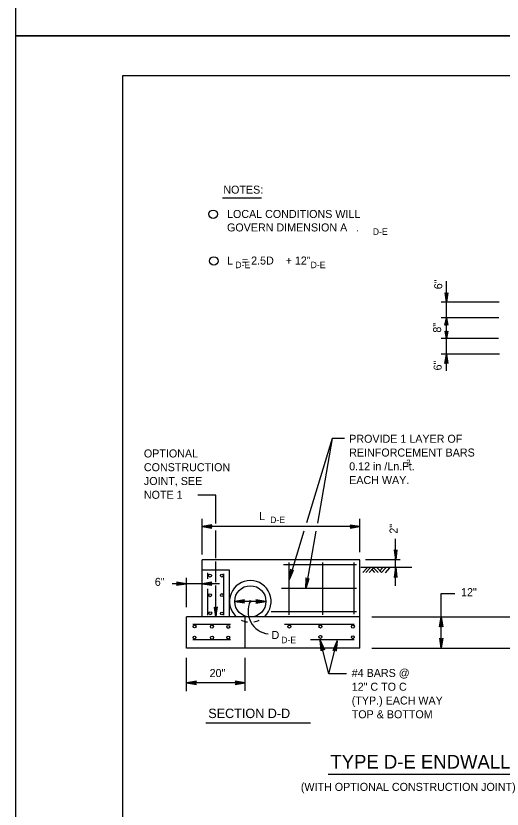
# Model space of a CAD drawing. Extents: x 638877 to 639960, y 297341 to 299123.
# Drawn here: x 638877.2 to 639059.3, y 298239.6 to 298536.8 of the extents above; entities that cross this region are included whole.
import ezdxf

# ---------------------------------------------------------------- set-up
doc = ezdxf.new("R2010")
doc.units = 0
for name, color, linetype in [('1', 7, 'Continuous'), ('2', 7, 'Continuous'), ('3', 7, 'Continuous'), ('PLT-BNDY', 7, 'Continuous')]:
    doc.layers.add(name, color=color, linetype=linetype)

msp = doc.modelspace()

# ---------------------------------------------------------------- linework, layer by layer
at = {"layer": '1'}
for p, q in [((639703.19, 298514.28), (638917.19, 298514.28)), ((638917.19, 298514.28), (638917.19, 297950.28)), ((639008.72, 298330.03), (639007.1, 298328.2)), ((639009.87, 298329.99), (639008.29, 298328.2)), ((639011.19, 298330.03), (639009.57, 298328.2)), ((639010.6, 298329.22), (639011.52, 298328.2)), ((639011.19, 298330.03), (639012.85, 298328.2)), ((639012.52, 298330.03), (639014.17, 298328.2)), ((639014.48, 298329.99), (639013.52, 298328.91)), ((639015.71, 298329.94), (639014.17, 298328.2)), ((639017.08, 298329.99), (639015.46, 298328.15)), ((639004.77, 298322.25), (638976.66, 298322.25))]:
    msp.add_line(p, q, dxfattribs=at)
for centre, radius in [((638951.08, 298462.44), 1.58), ((638951.33, 298444.95), 1.58), ((638949.9, 298327.08), 0.554), ((638954.36, 298327.08), 0.554), ((638949.94, 298319.73), 0.554), ((638954.36, 298319.78), 0.554), ((638965, 298317.42), 0.336), ((638949.98, 298312.98), 0.554), ((638954.36, 298312.88), 0.554), ((638944.11, 298308.02), 0.554), ((638950.61, 298307.95), 0.554), ((638956.74, 298307.86), 0.554), ((638979.62, 298307.98), 0.554), ((638991.26, 298307.97), 0.554), ((639003.44, 298307.95), 0.554), ((638944.09, 298303.86), 0.554), ((638950.66, 298303.84), 0.554), ((638956.74, 298303.89), 0.554), ((638991.24, 298304.1), 0.554), ((639003.4, 298304), 0.554)]:
    msp.add_circle(centre, radius, dxfattribs=at)
for centre, radius, start, end in [((638965, 298317.42), 7.8, 313.7868, 225.9644), ((638972.69, 298313.71), 8.53, 154.2808, 262.8901), ((638965, 298317.42), 7.8, 244.0182, 262.0844), ((638965, 298317.42), 7.8, 279.4238, 294.7753)]:
    msp.add_arc(centre, radius, start, end, dxfattribs=at)
at = {"layer": '2'}
for p, q in [((638969.21, 298468.52), (638954.55, 298468.52)), ((639038.48, 298423.69), (639038.48, 298437.42)), ((639038.48, 298429.54), (639038.48, 298435.42)), ((639058.18, 298429.54), (639036.51, 298429.54)), ((639058.06, 298423.69), (639036.51, 298423.69)), ((639038.48, 298415.89), (639038.48, 298423.69)), ((639057.91, 298415.89), (639036.51, 298415.89)), ((639038.48, 298403.78), (639038.48, 298415.89)), ((639058.32, 298410.04), (639036.51, 298410.04)), ((638995.69, 298378.46), (638986.04, 298346.88)), ((638995.69, 298378.46), (638990.11, 298346.73)), ((639000.22, 298378.46), (638995.69, 298378.46)), ((638952.07, 298357.24), (638945.34, 298357.24)), ((638952.07, 298346.58), (638952.07, 298357.24)), ((638946.93, 298335.04), (638946.93, 298348.32)), ((639006.08, 298335.8), (639006.08, 298348.32)), ((639006.08, 298345.44), (638946.93, 298345.44)), ((638952.07, 298333.67), (638952.07, 298344)), ((638985.09, 298343.78), (638979.51, 298325.52)), ((638989.58, 298343.72), (638985.8, 298322.25)), ((639019.44, 298323.27), (639019.44, 298340.86)), ((638946.93, 298311.57), (638946.93, 298333.02)), ((639006.08, 298333.02), (638946.93, 298333.02)), ((638952.07, 298324.57), (638952.07, 298332.41)), ((639004.77, 298331.07), (638977.44, 298331.07)), ((638979.51, 298312.43), (638979.51, 298331.95)), ((638992.14, 298312.43), (638992.14, 298331.95)), ((639003.86, 298312.58), (639003.86, 298331.95)), ((639006.08, 298299.87), (639006.08, 298333.02)), ((639021.11, 298333.02), (639008.14, 298333.02)), ((638957.2, 298329.12), (638946.93, 298329.12)), ((638949.13, 298325.86), (638949.13, 298328.12)), ((638957.2, 298311.57), (638957.2, 298329.12)), ((639025.55, 298330.07), (639006.4, 298330.07)), ((638941.08, 298315.19), (638941.08, 298326.3)), ((638955.03, 298312.24), (638955.03, 298327.74)), ((638946.93, 298324.03), (638935.73, 298324.03)), ((638953.45, 298324.03), (638946.93, 298324.03)), ((638949.13, 298312.24), (638949.13, 298322.11)), ((638952.07, 298311.57), (638952.07, 298323.4)), ((639036.52, 298299.87), (639036.52, 298320.37)), ((639036.52, 298320.37), (639041.62, 298320.37)), ((638970.85, 298317.42), (638959.15, 298317.42)), ((638965, 298317.42), (638965, 298317.42)), ((639004.77, 298313.56), (638972.84, 298313.56)), ((638946.93, 298311.57), (638941.08, 298311.57)), ((638941.08, 298299.87), (638941.08, 298311.57)), ((638957.2, 298311.57), (638946.93, 298311.57)), ((639006.08, 298311.57), (638957.2, 298311.57)), ((638963.05, 298299.87), (638963.05, 298311.57)), ((639010.52, 298311.57), (639062.52, 298311.57)), ((638957.6, 298308.7), (638943.44, 298308.7)), ((639003.88, 298308.7), (638977.85, 298308.7)), ((638957.6, 298303.03), (638943.44, 298303.03)), ((639003.88, 298303.03), (638987.49, 298303.03)), ((638994.39, 298290.29), (638991.18, 298302.86)), ((638994.39, 298290.29), (638997.57, 298302.65)), ((639006.08, 298299.87), (638941.08, 298299.87)), ((639010.52, 298299.87), (639062.52, 298299.87)), ((638941.08, 298283.83), (638941.08, 298296.31)), ((638963.05, 298283.93), (638963.05, 298296.25)), ((639000.97, 298290.29), (638994.39, 298290.29)), ((638963.05, 298286.88), (638941.08, 298286.88))]:
    msp.add_line(p, q, dxfattribs=at)
for points in [[(639038.89, 298432.85), (639038.65, 298432.73), (639038.48, 298429.54), (639038.89, 298432.85), (639039.04, 298433.02), (639038.48, 298429.54), (639038.32, 298432.72), (639038.08, 298432.84), (639038.48, 298429.54), (639037.93, 298433.02), (639038.08, 298432.84)], [(639038.06, 298421.04), (639038.3, 298421.14), (639038.48, 298423.68), (639038.06, 298421.04), (639037.92, 298420.9), (639038.48, 298423.68), (639038.63, 298421.14), (639038.87, 298421.05), (639038.48, 298423.68), (639039.03, 298420.9), (639038.87, 298421.05)], [(639038.89, 298418.56), (639038.65, 298418.46), (639038.48, 298415.92), (639038.89, 298418.56), (639039.04, 298418.7), (639038.48, 298415.92), (639038.32, 298418.46), (639038.08, 298418.56), (639038.48, 298415.92), (639037.93, 298418.7), (639038.08, 298418.56)], [(639038.06, 298406.74), (639038.3, 298406.86), (639038.48, 298410.04), (639038.06, 298406.74), (639037.92, 298406.57), (639038.48, 298410.04), (639038.63, 298406.86), (639038.87, 298406.75), (639038.48, 298410.04), (639039.03, 298406.57), (639038.87, 298406.75)], [(638950.47, 298345.88), (638950.34, 298345.63), (638946.93, 298345.44), (638950.47, 298345.88), (638950.65, 298346.04), (638946.93, 298345.44), (638950.33, 298345.27), (638950.46, 298345.02), (638946.93, 298345.44), (638950.65, 298344.85), (638950.46, 298345.02)], [(639002.54, 298344.99), (639002.67, 298345.25), (639006.08, 298345.44), (639002.54, 298344.99), (639002.36, 298344.84), (639006.08, 298345.44), (639002.67, 298345.61), (639002.55, 298345.86), (639006.08, 298345.44), (639002.36, 298346.03), (639002.55, 298345.86)], [(639019, 298336.59), (639019.26, 298336.46), (639019.45, 298333.05), (639019, 298336.59), (639018.85, 298336.77), (639019.45, 298333.05), (639019.62, 298336.46), (639019.87, 298336.58), (639019.45, 298333.05), (639020.04, 298336.77), (639019.87, 298336.58)], [(638980.14, 298329.21), (638980.36, 298329), (638979.51, 298325.52), (638980.14, 298329.21), (638980.04, 298329.44), (638979.51, 298325.52), (638980.71, 298328.89), (638981.01, 298328.93), (638979.51, 298325.52), (638981.23, 298329.07), (638981.01, 298328.93)], [(639019.89, 298326.51), (639019.63, 298326.65), (639019.45, 298330.06), (639019.89, 298326.51), (639020.05, 298326.33), (639019.45, 298330.06), (639019.28, 298326.65), (639019.03, 298326.52), (639019.45, 298330.06), (639018.85, 298326.33), (639019.03, 298326.52)], [(638985.97, 298325.99), (638986.21, 298325.81), (638985.8, 298322.25), (638985.97, 298325.99), (638985.84, 298326.2), (638985.8, 298322.25), (638986.58, 298325.74), (638986.86, 298325.83), (638985.8, 298322.25), (638987.07, 298325.99), (638986.86, 298325.83)], [(638937.54, 298323.58), (638937.67, 298323.84), (638941.08, 298324.03), (638937.54, 298323.58), (638937.36, 298323.43), (638941.08, 298324.03), (638937.67, 298324.2), (638937.55, 298324.45), (638941.08, 298324.03), (638937.36, 298324.62), (638937.55, 298324.45)], [(638950.47, 298324.47), (638950.34, 298324.22), (638946.93, 298324.03), (638950.47, 298324.47), (638950.65, 298324.63), (638946.93, 298324.03), (638950.33, 298323.86), (638950.46, 298323.61), (638946.93, 298324.03), (638950.65, 298323.44), (638950.46, 298323.61)], [(638962.69, 298317.86), (638962.56, 298317.6), (638959.15, 298317.42), (638962.69, 298317.86), (638962.88, 298318.02), (638959.15, 298317.42), (638962.56, 298317.25), (638962.68, 298316.99), (638959.15, 298317.42), (638962.88, 298316.82), (638962.68, 298316.99)], [(638967.31, 298316.97), (638967.44, 298317.23), (638970.85, 298317.42), (638967.31, 298316.97), (638967.13, 298316.81), (638970.85, 298317.42), (638967.45, 298317.58), (638967.32, 298317.84), (638970.85, 298317.42), (638967.13, 298318.01), (638967.32, 298317.84)], [(638951.62, 298315.11), (638951.88, 298314.97), (638952.07, 298311.57), (638951.62, 298315.11), (638951.47, 298315.29), (638952.07, 298311.57), (638952.23, 298314.97), (638952.49, 298315.1), (638952.07, 298311.57), (638952.66, 298315.29), (638952.49, 298315.1)], [(639036.07, 298308.02), (639036.33, 298308.16), (639036.52, 298311.57), (639036.07, 298308.02), (639035.92, 298307.84), (639036.52, 298311.57), (639036.69, 298308.16), (639036.94, 298308.03), (639036.52, 298311.57), (639037.11, 298307.84), (639036.94, 298308.03)], [(638991.64, 298299.14), (638991.87, 298299.35), (638991.18, 298302.86), (638991.64, 298299.14), (638991.53, 298298.92), (638991.18, 298302.86), (638992.23, 298299.44), (638992.52, 298299.38), (638991.18, 298302.86), (638992.74, 298299.23), (638992.52, 298299.38)], [(638996.2, 298299.18), (638996.5, 298299.24), (638997.57, 298302.65), (638996.2, 298299.18), (638995.99, 298299.03), (638997.57, 298302.65), (638996.86, 298299.16), (638997.08, 298298.96), (638997.57, 298302.65), (638997.2, 298298.72), (638997.08, 298298.96)], [(639036.96, 298303.41), (639036.71, 298303.27), (639036.52, 298299.87), (639036.96, 298303.41), (639037.12, 298303.59), (639036.52, 298299.87), (639036.35, 298303.27), (639036.1, 298303.4), (639036.52, 298299.87), (639035.93, 298303.59), (639036.1, 298303.4)], [(638944.62, 298287.33), (638944.49, 298287.07), (638941.08, 298286.88), (638944.62, 298287.33), (638944.8, 298287.48), (638941.08, 298286.88), (638944.48, 298286.71), (638944.61, 298286.46), (638941.08, 298286.88), (638944.8, 298286.29), (638944.61, 298286.46)], [(638959.51, 298286.44), (638959.64, 298286.7), (638963.05, 298286.88), (638959.51, 298286.44), (638959.33, 298286.28), (638963.05, 298286.88), (638959.65, 298287.05), (638959.52, 298287.3), (638963.05, 298286.88), (638959.33, 298287.48), (638959.52, 298287.3)]]:
    msp.add_lwpolyline(points, dxfattribs=at)
msp.add_circle((638965, 298317.42), 5.85, dxfattribs=at)
at = {"layer": '3'}
for p, q in [((638948.38, 298271.94), (638987.54, 298271.94)), ((638994.2, 298252.63), (639077.11, 298252.63))]:
    msp.add_line(p, q, dxfattribs=at)
at = {"layer": 'PLT-BNDY'}
for points in [[(638877.19, 299123.28), (639718.19, 299123.28), (639718.19, 298529.28), (638877.19, 298529.28)], [(638877.19, 298529.28), (639718.19, 298529.28), (639718.19, 297935.28), (638877.19, 297935.28)]]:
    msp.add_lwpolyline(points, close=True, dxfattribs=at)

# ---------------------------------------------------------------- texts
at = {"layer": '1'}
for s, height, p in [('NOTES:', 3, (638954.9, 298470.18)), ('LOCAL CONDITIONS WILL', 3, (638956.28, 298461.06)), ('GOVERN DIMENSION A   .', 3, (638956.28, 298456.02)), ('D-E', 2.43, (639010.88, 298454.73)), ('L   = 2.5D    + 12"', 3, (638956.28, 298443.61)), ('D-E', 2.43, (638959.38, 298442.25)), ('D-E', 2.43, (638987.59, 298442.25)), ('2', 2.16, (639023.43, 298368.37)), ('D-E', 2.43, (638972.43, 298346.75)), ('D', 3, (638972.96, 298303.32)), ('D-E', 2.43, (638976.57, 298301.74))]:
    msp.add_text(s, height=height, dxfattribs=at).set_placement(p)
msp.add_text('20"', height=3, rotation=360, dxfattribs=at).set_placement((638949.76, 298289.07))
at = {"layer": '2'}
msp.add_text('L', height=3, dxfattribs=at).set_placement((638968.32, 298347.85))
at = {"layer": '3'}
for s, p in [('6"', (639036.89, 298434.36)), ('8"', (639036.48, 298418.11)), ('6"', (639036.66, 298403.94)), ('2"', (639020.15, 298342.79))]:
    msp.add_text(s, height=3, rotation=90, dxfattribs=at).set_placement(p)
for s, height, p in [('PROVIDE 1 LAYER OF', 2.9999, (639002.04, 298376.85)), ('OPTIONAL', 3, (638925.14, 298371.34)), ('REINFORCEMENT BARS', 2.9999, (639002.04, 298371.69)), ('0.12 in /Ln.Ft.', 2.9999, (639002.04, 298366.53)), ('CONSTRUCTION', 2.9999, (638925.14, 298366.18)), ('JOINT, SEE', 3, (638925.14, 298361.02)), ('EACH WAY.', 3, (639002.04, 298361.37)), ('NOTE 1', 3, (638925.14, 298355.86)), ('6"', 3, (638929.22, 298323.23)), ('12"', 3, (639043.93, 298319.37)), ('#4 BARS @', 3, (639002.99, 298289.1)), ('12" C TO C', 3, (639002.99, 298283.94)), ('(TYP.) EACH WAY', 2.9999, (639002.99, 298278.78)), ('SECTION D-D', 3.5299, (638949.25, 298273.7)), ('TOP & BOTTOM', 2.9999, (639002.99, 298273.62)), ('TYPE D-E ENDWALL', 5.1858, (638995, 298254.74)), ('(WITH OPTIONAL CONSTRUCTION JOINT)', 2.9999, (638983.93, 298246.42))]:
    msp.add_text(s, height=height, dxfattribs=at).set_placement(p)

doc.saveas('drawing.dxf')
